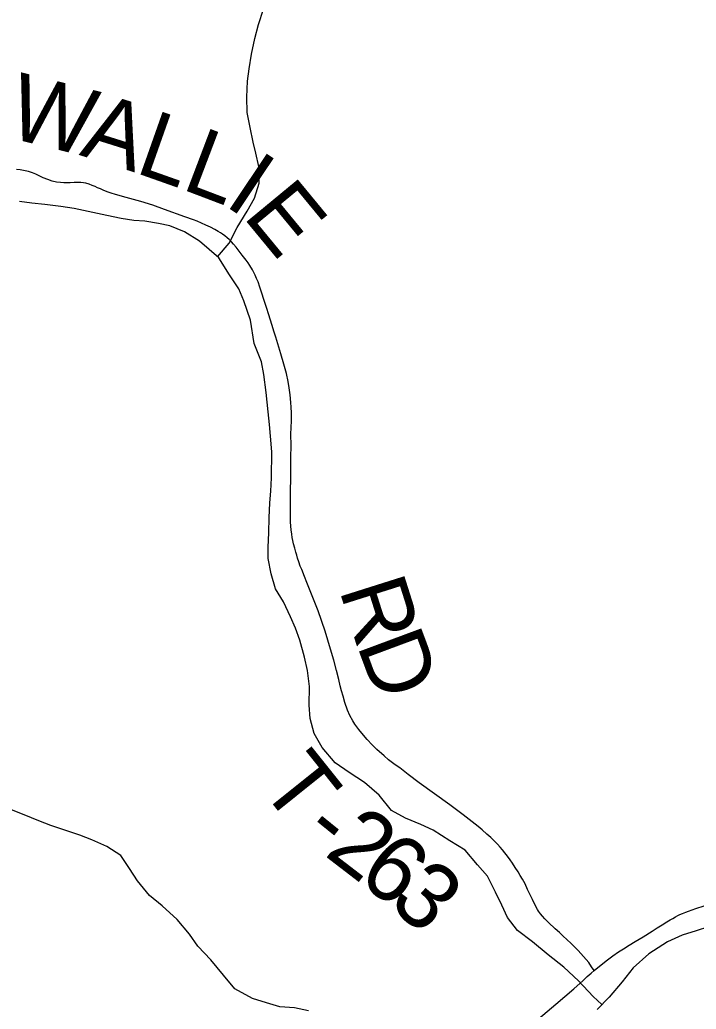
# Model space of a CAD drawing. Extents: x 0 to 34, y 0 to 22.
# Drawn here: x 5.781 to 6.359, y 18.618 to 19.464 of the extents above; entities that cross this region are included whole.
import ezdxf

# ---------------------------------------------------------------- set-up
doc = ezdxf.new("R2010")
doc.units = 0
for name, color, linetype in [('GM_X_County_Road', 7, 'Continuous'), ('GM_X_Minor_River', 7, 'Continuous'), ('GM_X_Township_Road', 7, 'Continuous'), ('GM_X_Township_Road_Text', 7, 'Continuous')]:
    doc.layers.add(name, color=color, linetype=linetype)

msp = doc.modelspace()

# ---------------------------------------------------------------- linework, layer by layer
at = {"layer": 'GM_X_County_Road'}
for points in [[(6.272, 18.6512), (6.27945, 18.65718), (6.28356, 18.66039), (6.288, 18.66368), (6.29293, 18.66713), (6.29721, 18.66984), (6.30206, 18.6728), (6.30724, 18.676), (6.3139, 18.68012), (6.32163, 18.68496), (6.32606, 18.68776), (6.33017, 18.69031), (6.33428, 18.69278), (6.33724, 18.6945), (6.33937, 18.69583), (6.3416, 18.69705), (6.34373, 18.6982), (6.34546, 18.69911), (6.34768, 18.70009), (6.3504, 18.70116), (6.35286, 18.70206), (6.35903, 18.7042), (6.36633, 18.70658)], [(6.22454, 18.60992), (6.23942, 18.62257), (6.25471, 18.63557), (6.2626, 18.6428), (6.26625, 18.64608), (6.26944, 18.64893), (6.272, 18.6512)]]:
    msp.add_lwpolyline(points, dxfattribs=at)
at = {"layer": 'GM_X_Minor_River'}
for points in [[(5.94995, 19.2612), (5.95989, 19.27306), (5.96688, 19.28624), (5.9754, 19.30016), (5.9816, 19.31145), (5.98556, 19.32429), (5.98535, 19.33833), (5.98284, 19.34974), (5.98031, 19.35925), (5.97781, 19.3718), (5.97532, 19.38473), (5.97511, 19.39763), (5.97566, 19.41127), (5.97693, 19.42187), (5.97898, 19.43436), (5.98181, 19.44797), (5.98499, 19.45969), (5.98933, 19.4729)], [(6.27867, 18.62211), (6.27138, 18.62909), (6.25866, 18.64254), (6.2463, 18.65409), (6.23278, 18.66451), (6.21927, 18.67569), (6.2065, 18.68534), (6.19792, 18.69645), (6.19313, 18.70714), (6.18758, 18.71821), (6.18093, 18.73195), (6.17233, 18.74155), (6.16187, 18.7542), (6.1487, 18.76197), (6.13441, 18.77126), (6.12386, 18.77595), (6.11066, 18.78144), (6.09861, 18.78805), (6.08816, 18.80108), (6.07578, 18.81187), (6.06262, 18.82039), (6.05059, 18.82889), (6.03938, 18.84194), (6.03271, 18.85378), (6.02908, 18.86673), (6.02846, 18.87811), (6.02866, 18.89404), (6.02694, 18.90771), (6.02443, 18.91912), (6.02045, 18.93359), (6.01678, 18.94388), (6.01235, 18.95342), (6.00645, 18.96639), (5.99939, 18.97748), (5.99576, 18.99043), (5.99327, 19.00336), (5.99338, 19.01284), (5.99393, 19.02572), (5.99409, 19.03823), (5.99463, 19.05112), (5.99551, 19.06097), (5.99603, 19.07234), (5.99631, 19.09471), (5.99534, 19.108), (5.99433, 19.11787), (5.99333, 19.12888), (5.99164, 19.14521), (5.98956, 19.16079), (5.98742, 19.17144), (5.98117, 19.18707), (5.97802, 19.20721), (5.97253, 19.22359), (5.96812, 19.23389), (5.9603, 19.24575), (5.95101, 19.26029), (5.93451, 19.27454), (5.92172, 19.28268), (5.90927, 19.28777), (5.89944, 19.2898), (5.88771, 19.29185), (5.87824, 19.29236), (5.86765, 19.29402), (5.85516, 19.29646), (5.83929, 19.30009), (5.82719, 19.30252), (5.81583, 19.30419), (5.8022, 19.30589), (5.79123, 19.30718), (5.78063, 19.30845)], [(6.02783, 18.61682), (6.01573, 18.61926), (6.00323, 18.62019), (5.9919, 18.62375), (5.97981, 18.62732), (5.96475, 18.63549), (5.95504, 18.64738), (5.94421, 18.66041), (5.93298, 18.67194), (5.92591, 18.68228), (5.91545, 18.69493), (5.90271, 18.70648), (5.89183, 18.71535), (5.88137, 18.728), (5.87468, 18.73833), (5.86723, 18.74943), (5.8552, 18.75717), (5.84238, 18.76304), (5.83219, 18.76696), (5.82011, 18.77092), (5.80728, 18.77526), (5.79709, 18.77919), (5.78464, 18.78429), (5.7737, 18.7886)], [(6.36994, 18.68844), (6.35929, 18.68517), (6.34749, 18.68154), (6.3349, 18.67564), (6.31885, 18.66562), (6.30543, 18.65366), (6.29618, 18.64166), (6.28502, 18.62853), (6.27465, 18.61805)]]:
    msp.add_lwpolyline(points, dxfattribs=at)
at = {"layer": 'GM_X_Township_Road'}
msp.add_lwpolyline([(6.272, 18.6512), (6.26992, 18.65435), (6.2675, 18.65795), (6.2652, 18.66079), (6.2606, 18.6658), (6.2583, 18.66824), (6.25518, 18.67149), (6.25207, 18.6746), (6.24896, 18.67758), (6.24543, 18.68083), (6.24246, 18.68381), (6.2388, 18.68692), (6.23298, 18.69233), (6.22987, 18.69531), (6.22784, 18.69762), (6.22608, 18.69965), (6.22463, 18.70187), (6.22377, 18.70336), (6.22201, 18.70641), (6.21931, 18.71196), (6.21511, 18.72062), (6.21295, 18.72523), (6.2109, 18.72931), (6.20888, 18.73254), (6.20703, 18.73569), (6.20457, 18.73935), (6.20219, 18.74288), (6.20017, 18.74594), (6.198, 18.74905), (6.19579, 18.7519), (6.1938, 18.75431), (6.19183, 18.75663), (6.18953, 18.75916), (6.18712, 18.76154), (6.18361, 18.76483), (6.18033, 18.76788), (6.17621, 18.77141), (6.17277, 18.77432), (6.16004, 18.78427), (6.14862, 18.79284), (6.12245, 18.81166), (6.11302, 18.81873), (6.10577, 18.82434), (6.10181, 18.82717), (6.09626, 18.83136), (6.0926, 18.83461), (6.08624, 18.84016), (6.08218, 18.84422), (6.07785, 18.84882), (6.07338, 18.8541), (6.07081, 18.85721), (6.06905, 18.85951), (6.06742, 18.86168), (6.06567, 18.86466), (6.06323, 18.86926), (6.06106, 18.87373), (6.05876, 18.88036), (6.05727, 18.88578), (6.05605, 18.89038), (6.05497, 18.89458), (6.05375, 18.89999), (6.05172, 18.90757), (6.04929, 18.91637), (6.04671, 18.92584), (6.04197, 18.94142), (6.03602, 18.95874), (6.02632, 18.98291), (6.02431, 18.98801), (6.02198, 18.99388), (6.02077, 18.99697), (6.01954, 19.0005), (6.01847, 19.00382), (6.01773, 19.00626), (6.01699, 19.00889), (6.01607, 19.01212), (6.01502, 19.01604), (6.01436, 19.01875), (6.01387, 19.02138), (6.01337, 19.02434), (6.01292, 19.02787), (6.01246, 19.03441), (6.01246, 19.04564), (6.01246, 19.05797), (6.0126, 19.07489), (6.01274, 19.08978), (6.01287, 19.10006), (6.01274, 19.10954), (6.01314, 19.12118), (6.01328, 19.12795), (6.013, 19.13282), (6.01274, 19.13675), (6.01206, 19.14325), (6.01125, 19.14921), (6.0103, 19.15476), (6.00881, 19.16139), (6.00664, 19.16951), (6.00407, 19.17831), (6.0015, 19.18684), (5.99974, 19.19252), (5.99833, 19.19682), (5.99636, 19.20346), (5.9938, 19.21159), (5.99183, 19.21793), (5.98994, 19.22401), (5.98766, 19.23111), (5.98625, 19.23527), (5.98461, 19.2399), (5.98337, 19.24284), (5.98222, 19.24563), (5.98107, 19.24793), (5.97997, 19.25005), (5.9777, 19.25375), (5.97605, 19.25615), (5.97445, 19.2583), (5.97104, 19.26281), (5.9684, 19.26619), (5.96586, 19.26939), (5.9637, 19.27198), (5.96183, 19.27407), (5.95982, 19.27599), (5.95813, 19.27752), (5.95607, 19.27926), (5.95427, 19.28057), (5.95255, 19.28179), (5.95049, 19.28303), (5.9477, 19.28456), (5.94391, 19.28648), (5.93991, 19.28841), (5.9361, 19.2901), (5.93251, 19.2916), (5.92931, 19.29276), (5.92201, 19.2954), (5.90454, 19.30184), (5.89457, 19.3053), (5.88448, 19.30842), (5.87192, 19.31192), (5.86253, 19.31452), (5.85909, 19.31557), (5.85645, 19.31657), (5.85275, 19.31805), (5.84975, 19.31923), (5.84732, 19.32035), (5.84518, 19.32134), (5.84285, 19.32229), (5.84003, 19.3234), (5.83737, 19.32414), (5.83529, 19.32451), (5.83297, 19.32491), (5.83053, 19.32491), (5.82728, 19.32478), (5.82403, 19.32451), (5.82119, 19.32451), (5.81861, 19.32451), (5.81564, 19.32465), (5.81212, 19.32519), (5.8086, 19.326), (5.80467, 19.32722), (5.80086, 19.32887), (5.798, 19.33015), (5.79452, 19.33182), (5.79168, 19.33303), (5.78814, 19.33409), (5.78105, 19.33557), (5.77799, 19.33596)], dxfattribs=at)

# ---------------------------------------------------------------- texts
at = {"layer": 'GM_X_Township_Road_Text'}
for s, rotation, p in [('W', 346.19464, (5.76795, 19.36392)), ('A', 342.59752, (5.83097, 19.34846)), ('L', 340.52895, (5.87817, 19.33368)), ('L', 339.18564, (5.91791, 19.31963)), ('I', 326.19465, (5.95462, 19.30609)), ('E', 309.53999, (5.97078, 19.29603)), ('R', 287.53146, (6.05375, 18.97712)), ('D', 290.39769, (6.0688, 18.92973)), ('T', 308.6558, (5.98494, 18.8086)), ('-', 321.01841, (6.02089, 18.76595)), ('2', 322.50015, (6.04029, 18.75028)), ('6', 322.5966, (6.06814, 18.72891)), ('3', 317.9157, (6.095, 18.70844))]:
    msp.add_text(s, height=0.05682, rotation=rotation, dxfattribs=at).set_placement(p)

doc.saveas('drawing.dxf')
